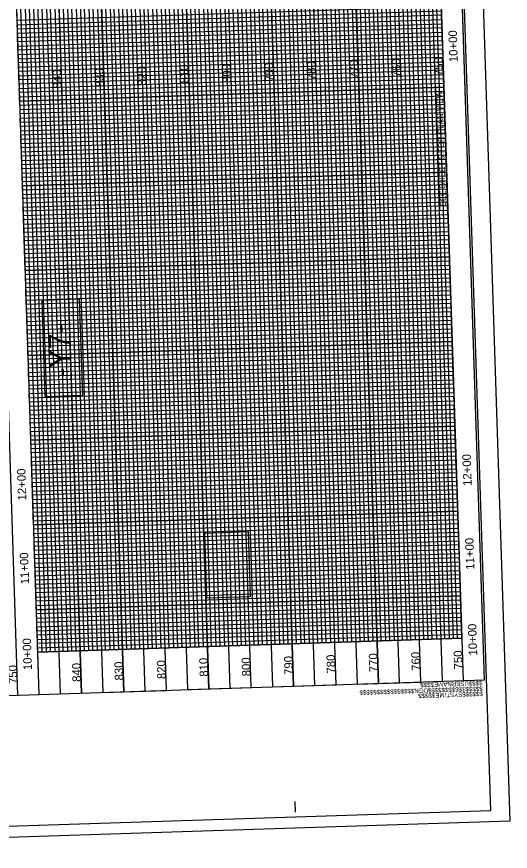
# Model space of a CAD drawing. Extents: x 1627314 to 1628469, y 762309 to 764247.
# Drawn here: x 1627888 to 1628469, y 762309 to 763293 of the extents above; entities that cross this region are included whole.
import ezdxf

# ---------------------------------------------------------------- set-up
doc = ezdxf.new("R2010")
doc.units = 0
for name, color, linetype in [('Exist Vertical Profile Horizontal Axis Label Major', 7, 'Continuous'), ('Exist Vertical Profile Vertical Axis Label', 7, 'Continuous'), ('Prop DSN Text', 7, 'Continuous'), ('Prop Grid Mask', 7, 'Continuous'), ('Sheet Data Field CELL', 7, 'Continuous'), ('Sheet DOT Grid CELL', 7, 'Continuous'), ('Sheet Layout Profile Border Port 2', 7, 'Continuous'), ('Sheet Plot Border Inside CELL', 7, 'Continuous'), ('Sheet Plot Border Outside CELL', 7, 'Continuous'), ('Sheet Profile CELL', 7, 'Continuous'), ('Sheet Profile Grid Major CELL', 7, 'Continuous'), ('Sheet Profile Grid Middle CELL', 7, 'Continuous'), ('Sheet Profile Grid Minor CELL', 7, 'Continuous')]:
    doc.layers.add(name, color=color, linetype=linetype)

msp = doc.modelspace()

# ---------------------------------------------------------------- linework, layer by layer
at = {"layer": 'Prop Grid Mask'}
for points in [[(1627891.16, 763193.83), (1627889.52, 763243.8), (1628389.25, 763260.15), (1628390.89, 763210.18)], [(1628380.89, 763209.85), (1628385.63, 763064.93), (1628395.63, 763065.25), (1628390.89, 763210.18)], [(1627965.43, 762847.15), (1627961.73, 762960.18), (1627917.01, 762958.71), (1627920.71, 762845.69)], [(1628111.66, 762607.67), (1628109.14, 762684.58), (1628160.29, 762686.26), (1628162.8, 762609.35)]]:
    msp.add_lwpolyline(points, close=True, dxfattribs=at)
at = {"layer": 'Sheet DOT Grid CELL'}
for p, q in [((1628163.91, 762502.38), (1628114.87, 764001.46)), ((1628213.88, 762504.01), (1628164.85, 764003.1)), ((1628263.85, 762505.65), (1628214.82, 764004.73)), ((1628313.83, 762507.28), (1628264.79, 764006.37)), ((1628363.8, 762508.92), (1628314.77, 764008)), ((1627914.04, 762494.2), (1627865.01, 763993.29)), ((1627964.01, 762495.84), (1627914.98, 763994.92)), ((1628013.99, 762497.47), (1627964.95, 763996.56)), ((1628063.96, 762499.11), (1628014.93, 763998.19)), ((1628113.93, 762500.74), (1628064.9, 763999.83)), ((1627889.52, 763243.8), (1628389.25, 763260.15)), ((1627891.16, 763193.83), (1628390.89, 763210.18)), ((1627892.79, 763143.86), (1628392.52, 763160.2)), ((1627894.43, 763093.88), (1628394.16, 763110.23)), ((1627896.06, 763043.91), (1628395.79, 763060.26)), ((1627897.69, 762993.94), (1628397.43, 763010.28)), ((1627899.33, 762943.96), (1628399.06, 762960.31)), ((1627900.96, 762893.99), (1628400.7, 762910.34)), ((1627902.6, 762844.02), (1628402.33, 762860.36)), ((1627904.23, 762794.04), (1628403.97, 762810.39)), ((1627905.87, 762744.07), (1628405.6, 762760.42)), ((1627907.5, 762694.1), (1628407.24, 762710.44)), ((1627909.14, 762644.12), (1628408.87, 762660.47)), ((1627910.77, 762594.15), (1628410.5, 762610.5)), ((1627912.41, 762544.18), (1628412.14, 762560.52))]:
    msp.add_line(p, q, dxfattribs=at)
at = {"layer": 'Sheet Layout Profile Border Port 2'}
msp.add_lwpolyline([(1627912.41, 762544.18), (1627866.64, 763943.43), (1628366.37, 763959.78), (1628412.14, 762560.52)], close=True, dxfattribs=at)
at = {"layer": 'Sheet Plot Border Inside CELL'}
msp.add_lwpolyline([(1628446.34, 762357.53), (1628391.86, 764023.14), (1627337.33, 763988.65), (1627391.81, 762323.04)], close=True, dxfattribs=at)
at = {"layer": 'Sheet Plot Border Outside CELL'}
msp.add_lwpolyline([(1628469.21, 762345.27), (1628413.63, 764044.37), (1627314.22, 764008.4), (1627369.79, 762309.31)], close=True, dxfattribs=at)
at = {"layer": 'Sheet Profile CELL'}
for p, q in [((1628364.74, 764009.75), (1628413.77, 762510.55)), ((1628438.76, 762511.37), (1628389.72, 764010.57)), ((1627889.05, 762493.39), (1627840.02, 763992.59)), ((1627914.04, 762494.2), (1627865, 763993.4)), ((1628438.76, 762511.37), (1628438.76, 762511.37)), ((1628438.76, 762511.37), (1628438.76, 762511.37)), ((1628438.76, 762511.37), (1628438.76, 762511.37)), ((1628438.76, 762511.37), (1628438.76, 762511.37)), ((1628438.76, 762511.37), (1628438.76, 762511.37)), ((1628438.76, 762511.37), (1628438.76, 762511.37)), ((1628438.76, 762511.37), (1628438.76, 762511.37)), ((1628216.24, 762355.51), (1628215.83, 762368))]:
    msp.add_line(p, q, dxfattribs=at)
msp.add_lwpolyline([(1627340.28, 763976.24), (1627389.32, 762477.04), (1628438.76, 762511.37), (1628389.72, 764010.57)], close=True, dxfattribs=at)
msp.add_lwpolyline([(1628437.53, 762548.85), (1628437.53, 762548.85)], dxfattribs=at)
at = {"layer": 'Sheet Profile Grid Major CELL'}
for p, q in [((1627891.16, 763193.83), (1627889.52, 763243.8)), ((1627894.43, 763093.88), (1627892.79, 763143.86)), ((1627897.69, 762993.94), (1627896.06, 763043.91)), ((1628413.77, 762510.55), (1628413.77, 762510.55))]:
    msp.add_line(p, q, dxfattribs=at)
for points in [[(1628064.9, 763999.94), (1628113.93, 762500.74), (1628163.91, 762502.38), (1628114.87, 764001.58)], [(1628164.84, 764003.21), (1628213.88, 762504.01), (1628263.85, 762505.65), (1628214.82, 764004.85)], [(1628264.79, 764006.48), (1628313.83, 762507.28), (1628313.83, 762507.28), (1628363.8, 762508.92), (1628314.76, 764008.11)], [(1628364.74, 764009.75), (1628413.77, 762510.55)], [(1627914.98, 763995.04), (1627964.01, 762495.84)], [(1627964.95, 763996.67), (1628013.99, 762497.47), (1628063.96, 762499.11), (1628014.92, 763998.31)], [(1627912.41, 762544.18), (1628412.14, 762560.52), (1628410.5, 762610.5), (1627910.77, 762594.15), (1627909.14, 762644.12), (1628408.87, 762660.47), (1628407.24, 762710.44), (1627907.5, 762694.1), (1627905.87, 762744.07), (1628405.6, 762760.42), (1628403.97, 762810.39), (1627904.23, 762794.04), (1627902.6, 762844.02), (1628402.33, 762860.36), (1628400.7, 762910.34), (1627900.96, 762893.99), (1627899.33, 762943.96), (1628399.06, 762960.31), (1628397.43, 763010.28), (1627897.69, 762993.94), (1627896.06, 763043.91), (1628395.79, 763060.26), (1628394.16, 763110.23), (1627894.43, 763093.88), (1627892.79, 763143.86), (1628392.52, 763160.2), (1628390.89, 763210.18), (1627891.16, 763193.83), (1627889.52, 763243.8), (1628389.25, 763260.15), (1628387.62, 763310.12)]]:
    msp.add_lwpolyline(points, dxfattribs=at)
at = {"layer": 'Sheet Profile Grid Middle CELL'}
for points in [[(1628139.86, 764002.39), (1628188.89, 762503.2), (1628238.87, 762504.83), (1628189.83, 764004.03)], [(1628239.8, 764005.66), (1628288.84, 762506.46), (1628338.81, 762508.1), (1628289.78, 764007.3)], [(1628339.75, 764008.93), (1628388.79, 762509.73)], [(1627939.03, 762495.02), (1627889.99, 763994.22)], [(1627939.96, 763995.85), (1627989, 762496.66), (1628038.97, 762498.29), (1627989.94, 763997.49)], [(1628039.91, 763999.12), (1628088.95, 762499.93), (1628138.92, 762501.56), (1628089.88, 764000.76)], [(1627913.22, 762519.19), (1627911.59, 762569.16), (1628411.32, 762585.51), (1628409.69, 762635.48), (1627909.95, 762619.14), (1627908.32, 762669.11), (1628408.05, 762685.46), (1628406.42, 762735.43), (1627906.69, 762719.08), (1627905.05, 762769.06), (1628404.78, 762785.4), (1628403.15, 762835.38), (1627903.42, 762819.03), (1627901.78, 762869), (1628401.51, 762885.35), (1628399.88, 762935.32), (1627900.15, 762918.98), (1627898.51, 762968.95), (1628398.24, 762985.3), (1628396.61, 763035.27), (1627896.88, 763018.92), (1627895.24, 763068.9), (1628394.98, 763085.24), (1628393.34, 763135.22), (1628393.34, 763135.22), (1627893.61, 763118.87), (1627891.97, 763168.84), (1628391.71, 763185.19), (1628390.07, 763235.16), (1627890.34, 763218.82), (1627888.7, 763268.79), (1628388.44, 763285.14), (1628386.8, 763335.11)]]:
    msp.add_lwpolyline(points, dxfattribs=at)
at = {"layer": 'Sheet Profile Grid Minor CELL'}
for p, q in [((1628167.27, 762552.51), (1628121.5, 763951.77)), ((1628126.5, 763951.93), (1628172.27, 762552.68)), ((1628177.26, 762552.84), (1628131.5, 763952.09)), ((1628136.49, 763952.26), (1628182.26, 762553)), ((1628192.26, 762553.33), (1628146.49, 763952.58)), ((1628151.48, 763952.75), (1628197.25, 762553.5)), ((1628202.25, 762553.66), (1628156.48, 763952.91)), ((1628161.48, 763953.07), (1628207.25, 762553.82)), ((1628217.24, 762554.15), (1628171.47, 763953.4)), ((1628176.47, 763953.56), (1628222.24, 762554.31)), ((1628227.24, 762554.48), (1628181.47, 763953.73)), ((1628186.47, 763953.89), (1628232.24, 762554.64)), ((1628242.23, 762554.97), (1628196.46, 763954.22)), ((1628201.46, 763954.38), (1628247.23, 762555.13)), ((1628252.22, 762555.29), (1628206.46, 763954.55)), ((1628211.45, 763954.71), (1628257.22, 762555.46)), ((1628267.22, 762555.78), (1628221.45, 763955.04)), ((1628226.44, 763955.2), (1628272.21, 762555.95)), ((1628277.21, 762556.11), (1628231.44, 763955.36)), ((1628236.44, 763955.53), (1628282.21, 762556.27)), ((1628292.2, 762556.6), (1628246.43, 763955.85)), ((1628251.43, 763956.02), (1628297.2, 762556.76)), ((1628302.2, 762556.93), (1628256.43, 763956.18)), ((1628261.43, 763956.34), (1628307.2, 762557.09)), ((1628317.19, 762557.42), (1628271.42, 763956.67)), ((1628276.42, 763956.83), (1628322.19, 762557.58)), ((1628327.18, 762557.75), (1628281.42, 763957)), ((1628286.41, 763957.16), (1628332.18, 762557.91)), ((1628342.18, 762558.24), (1628296.41, 763957.49)), ((1628301.4, 763957.65), (1628347.17, 762558.4)), ((1628352.17, 762558.56), (1628306.4, 763957.81)), ((1628311.4, 763957.98), (1628357.17, 762558.73)), ((1628367.16, 762559.05), (1628321.39, 763958.3)), ((1628326.39, 763958.47), (1628372.16, 762559.22)), ((1628377.16, 762559.38), (1628331.39, 763958.63)), ((1628336.39, 763958.8), (1628382.16, 762559.54)), ((1628392.15, 762559.87), (1628346.38, 763959.12)), ((1628351.38, 763959.29), (1628397.15, 762560.03)), ((1628402.14, 762560.2), (1628356.37, 763959.45)), ((1628407.14, 762560.36), (1628361.37, 763959.61)), ((1627917.4, 762544.34), (1627871.63, 763943.59)), ((1627876.63, 763943.76), (1627922.4, 762544.5)), ((1627927.4, 762544.67), (1627881.63, 763943.92)), ((1627886.63, 763944.08), (1627932.4, 762544.83)), ((1627942.39, 762545.16), (1627896.62, 763944.41)), ((1627901.62, 763944.57), (1627947.39, 762545.32)), ((1627952.38, 762545.49), (1627906.62, 763944.74)), ((1627911.61, 763944.9), (1627957.38, 762545.65)), ((1627967.38, 762545.98), (1627921.61, 763945.23)), ((1627926.6, 763945.39), (1627972.37, 762546.14)), ((1627977.37, 762546.3), (1627931.6, 763945.55)), ((1627936.6, 763945.72), (1627982.37, 762546.47)), ((1627992.36, 762546.79), (1627946.59, 763946.05)), ((1627951.59, 763946.21), (1627997.36, 762546.96)), ((1628002.36, 762547.12), (1627956.59, 763946.37)), ((1627961.59, 763946.54), (1628007.36, 762547.28)), ((1628017.35, 762547.61), (1627971.58, 763946.86)), ((1627976.58, 763947.03), (1628022.35, 762547.77)), ((1628027.34, 762547.94), (1627981.58, 763947.19)), ((1627986.57, 763947.35), (1628032.34, 762548.1)), ((1628042.34, 762548.43), (1627996.57, 763947.68)), ((1628001.56, 763947.84), (1628047.33, 762548.59)), ((1628052.33, 762548.75), (1628006.56, 763948.01)), ((1628011.56, 763948.17), (1628057.33, 762548.92)), ((1628067.32, 762549.25), (1628021.55, 763948.5)), ((1628026.55, 763948.66), (1628072.32, 762549.41)), ((1628077.32, 762549.57), (1628031.55, 763948.82)), ((1628036.55, 763948.99), (1628082.32, 762549.74)), ((1628092.31, 762550.06), (1628046.54, 763949.31)), ((1628051.54, 763949.48), (1628097.31, 762550.23)), ((1628102.3, 762550.39), (1628056.54, 763949.64)), ((1628061.53, 763949.8), (1628107.15, 762550.55)), ((1628117.3, 762550.88), (1628071.53, 763950.13)), ((1628076.52, 763950.3), (1628122.29, 762551.04)), ((1628127.29, 762551.21), (1628081.52, 763950.46)), ((1628086.52, 763950.62), (1628132.29, 762551.37)), ((1628142.28, 762551.7), (1628096.51, 763950.95)), ((1628101.51, 763951.11), (1628147.28, 762551.86)), ((1628152.28, 762552.02), (1628106.51, 763951.28)), ((1628111.51, 763951.44), (1628157.28, 762552.19))]:
    msp.add_line(p, q, dxfattribs=at)
for points in [[(1628387.78, 763305.13), (1627888.05, 763288.78), (1627887.72, 763298.77)], [(1627895.08, 763073.89), (1628394.81, 763090.24), (1628394.65, 763095.24), (1627894.92, 763078.89), (1627894.75, 763083.89), (1628394.49, 763100.24), (1628394.32, 763105.23), (1627894.59, 763088.89), (1627894.26, 763098.88), (1628393.99, 763115.23), (1628393.83, 763120.22), (1627894.1, 763103.88), (1627893.94, 763108.88), (1628393.67, 763125.22), (1628393.5, 763130.22), (1627893.77, 763113.87), (1627893.44, 763123.87), (1628393.18, 763140.21), (1628393.01, 763145.21), (1627893.28, 763128.87), (1627893.12, 763133.86), (1628392.85, 763150.21), (1628392.69, 763155.21), (1627892.95, 763138.86), (1627892.63, 763148.85), (1628392.36, 763165.2), (1628392.2, 763170.2), (1627892.46, 763153.85), (1627892.3, 763158.85), (1628392.03, 763175.2), (1628391.87, 763180.19), (1627892.14, 763163.85), (1627891.81, 763173.84), (1628391.54, 763190.19), (1628391.38, 763195.18), (1627891.65, 763178.84), (1627891.48, 763183.84), (1628391.22, 763200.18), (1628391.05, 763205.18), (1627891.32, 763188.83), (1627890.99, 763198.83), (1628390.73, 763215.17), (1628390.73, 763215.17), (1628390.56, 763220.17), (1627890.83, 763203.83), (1627890.67, 763208.82), (1628390.4, 763225.17), (1628390.24, 763230.17), (1627890.5, 763213.82), (1627890.18, 763223.81), (1628389.91, 763240.16), (1628389.74, 763245.16), (1627890.01, 763228.81), (1627889.85, 763233.81), (1628389.58, 763250.16), (1628389.42, 763255.15), (1627889.69, 763238.81), (1627889.36, 763248.8), (1628389.09, 763265.15), (1628388.93, 763270.14), (1627889.19, 763253.8), (1627889.03, 763258.8), (1628388.76, 763275.14), (1628388.6, 763280.14), (1627888.87, 763263.79), (1627888.54, 763273.79), (1628388.27, 763290.13), (1628388.11, 763295.13), (1627888.38, 763278.79), (1627888.21, 763283.78), (1628387.95, 763300.13)], [(1628405.11, 762775.41), (1628404.95, 762780.41), (1627905.21, 762764.06), (1627904.89, 762774.06), (1628404.62, 762790.4), (1628404.46, 762795.4), (1627904.72, 762779.05), (1627904.56, 762784.05), (1628404.29, 762800.4), (1628404.13, 762805.39), (1627904.4, 762789.05), (1627904.07, 762799.04), (1628403.8, 762815.39), (1628403.64, 762820.39), (1627903.91, 762804.04), (1627903.74, 762809.04), (1628403.48, 762825.38), (1628403.31, 762830.38), (1627903.58, 762814.03), (1627903.25, 762824.03), (1628402.99, 762840.37), (1628402.82, 762845.37), (1627903.09, 762829.03), (1627902.93, 762834.02), (1628402.66, 762850.37), (1628402.49, 762855.37), (1627902.76, 762839.02), (1627902.44, 762849.01), (1628402.17, 762865.36), (1628402, 762870.36), (1627902.27, 762854.01), (1627902.11, 762859.01), (1628401.84, 762875.36), (1628401.68, 762880.35), (1627901.94, 762864.01), (1627901.62, 762874), (1628401.35, 762890.35), (1628401.19, 762895.35), (1627901.45, 762879), (1627901.29, 762884), (1628401.02, 762900.34), (1628400.86, 762905.34), (1627901.13, 762888.99), (1627900.8, 762898.99), (1628400.53, 762915.33), (1628400.37, 762920.33), (1627900.64, 762903.99), (1627900.47, 762908.98), (1628400.21, 762925.33), (1628400.04, 762930.33), (1627900.31, 762913.98), (1627899.98, 762923.97), (1628399.72, 762940.32), (1628399.55, 762945.32), (1627899.82, 762928.97), (1627899.66, 762933.97), (1628399.39, 762950.32), (1628399.23, 762955.31), (1627899.49, 762938.97), (1627899.17, 762948.96), (1628398.9, 762965.31), (1628398.74, 762970.31), (1627899, 762953.96), (1627898.84, 762958.96), (1628398.57, 762975.3), (1628398.41, 762980.3), (1627898.68, 762963.95), (1627898.35, 762973.95), (1628398.08, 762990.29), (1628397.92, 762995.29), (1627898.19, 762978.95), (1627898.02, 762983.94), (1628397.75, 763000.29), (1628397.59, 763005.29), (1627897.86, 762988.94), (1627897.53, 762998.93), (1628397.26, 763015.28), (1628397.1, 763020.28), (1627897.37, 763003.93), (1627897.2, 763008.93), (1628396.94, 763025.28), (1628396.77, 763030.27), (1627897.04, 763013.93), (1627896.71, 763023.92), (1628396.45, 763040.27), (1628396.28, 763045.26), (1627896.55, 763028.92), (1627896.39, 763033.92), (1628396.12, 763050.26), (1628395.96, 763055.26), (1627896.22, 763038.91), (1627895.9, 763048.91), (1628395.63, 763065.25), (1628395.47, 763070.25), (1627895.73, 763053.91), (1627895.57, 763058.9), (1628395.3, 763075.25), (1628395.14, 763080.25), (1627895.41, 763063.9), (1627895.08, 763073.89)], [(1627912.41, 762544.18), (1627912.24, 762549.18), (1628411.98, 762565.52), (1628411.81, 762570.52), (1627912.08, 762554.17), (1627911.92, 762559.17), (1628411.65, 762575.52), (1628411.49, 762580.51), (1627911.75, 762564.17), (1627911.43, 762574.16), (1628411.16, 762590.51), (1628410.99, 762595.51), (1627911.26, 762579.16), (1627911.1, 762584.16), (1628410.83, 762600.5), (1628410.67, 762605.5), (1628410.34, 762615.49), (1628410.18, 762620.49), (1627910.44, 762604.15), (1627910.28, 762609.14), (1628410.01, 762625.49), (1628409.85, 762630.49), (1627910.12, 762614.14), (1627909.79, 762624.14), (1628409.52, 762640.48), (1628409.36, 762645.48), (1627909.63, 762629.13), (1627909.46, 762634.13), (1628409.2, 762650.48), (1628409.03, 762655.47), (1627909.3, 762639.13), (1627908.97, 762649.12), (1628408.71, 762665.47), (1628408.54, 762670.47), (1627908.81, 762654.12), (1627908.65, 762659.12), (1628408.38, 762675.46), (1628408.22, 762680.46), (1627908.48, 762664.11), (1627908.16, 762674.11), (1628407.89, 762690.45), (1628407.73, 762695.45), (1627907.99, 762679.11), (1627907.83, 762684.1), (1628407.56, 762700.45), (1628407.4, 762705.45), (1627907.67, 762689.1), (1627907.34, 762699.1), (1628407.07, 762715.44), (1628406.91, 762720.44), (1627907.18, 762704.09), (1627907.01, 762709.09), (1628406.74, 762725.44), (1628406.58, 762730.43), (1627906.85, 762714.09), (1627906.52, 762724.08), (1628406.25, 762740.43), (1628406.09, 762745.43), (1627906.36, 762729.08), (1627906.19, 762734.08), (1628405.93, 762750.42), (1628405.76, 762755.42), (1627906.03, 762739.07), (1627905.7, 762749.07), (1628405.44, 762765.41), (1628405.27, 762770.41), (1627905.54, 762754.07), (1627905.38, 762759.06), (1628405.11, 762775.41)], [(1628410.67, 762605.5), (1627910.94, 762589.15), (1627910.61, 762599.15), (1628410.34, 762615.49)]]:
    msp.add_lwpolyline(points, dxfattribs=at)

# ---------------------------------------------------------------- texts
at = {"layer": 'Exist Vertical Profile Horizontal Axis Label Major'}
for s, p in [('10+00', (1628407.43, 763239.93)), ('12+00', (1628423.77, 762740.31)), ('12+00', (1627899.05, 762723.15)), ('11+00', (1628427, 762641.45)), ('11+00', (1627902.28, 762624.28)), ('10+00', (1628430.31, 762540.3)), ('10+00', (1627905.59, 762523.14))]:
    msp.add_text(s, height=10, rotation=91.87347, dxfattribs=at).set_placement(p)
at = {"layer": 'Exist Vertical Profile Vertical Axis Label'}
for s, p in [('760', (1628340.23, 763221.96)), ('750', (1628390.2, 763223.59)), ('820', (1628040.39, 763212.15)), ('810', (1628090.32, 763214.98)), ('800', (1628140.33, 763215.42)), ('790', (1628190.31, 763217.05)), ('780', (1628240.28, 763218.69)), ('770', (1628290.25, 763220.32)), ('840', (1627940.44, 763208.88)), ('830', (1627990.41, 763210.52)), ('750', (1628413.08, 762523.97)), ('810', (1628113.21, 762515.36)), ('800', (1628163.22, 762515.79)), ('790', (1628213.19, 762517.43)), ('780', (1628263.16, 762519.06)), ('770', (1628313.14, 762520.7)), ('760', (1628363.11, 762522.33)), ('750', (1627888.37, 762506.8)), ('840', (1627963.33, 762509.26)), ('830', (1628013.3, 762510.89)), ('820', (1628063.27, 762512.53))]:
    msp.add_text(s, height=10, rotation=91.87347, dxfattribs=at).set_placement(p)
at = {"layer": 'Prop DSN Text'}
msp.add_text('SEE SHEET 5 FOR PLAN VIEW', height=7, rotation=91.87347, dxfattribs=at).set_placement((1628393.53, 763069.77))
at = {"layer": 'Sheet Data Field CELL'}
msp.add_text('-Y7-', height=25, rotation=91.87347, dxfattribs=at).set_placement((1627951.67, 762868.44))
at = {"layer": 'Sheet Profile CELL'}
for s, p in [('$$$$USERNAME$$$$', (1628436.41, 762510.23)), ('$$$$$$$$$$$$$$$$DGN$$$$$$$$$$$$$$$$', (1628436.64, 762503.66)), ('$$$$$$SYSTIME$$$$$', (1628436.83, 762497.61))]:
    msp.add_text(s, height=5.25, rotation=181.87347, dxfattribs=at).set_placement(p)

doc.saveas('drawing.dxf')
